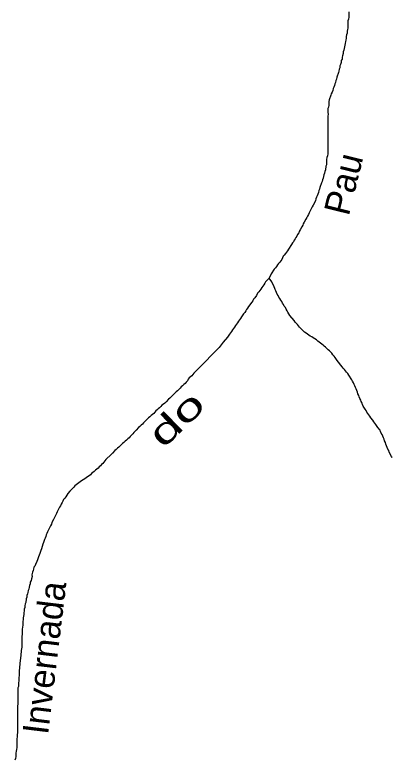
# Model space of a CAD drawing. Extents: x 652.3 to 678, y 7316.9 to 7344.9.
# Drawn here: x 662.24 to 663.41, y 7328.056 to 7330.367 of the extents above; entities that cross this region are included whole.
import ezdxf
from ezdxf.enums import TextEntityAlignment as Align

# ---------------------------------------------------------------- set-up
doc = ezdxf.new("R2010")
doc.units = 0
doc.header["$LTSCALE"] = 0.032
doc.layers.add('61', color=7, linetype='Continuous')
doc.layers.add('7', color=7, linetype='Continuous', lineweight=25)

msp = doc.modelspace()

# ---------------------------------------------------------------- linework, layer by layer
at = {"layer": '7'}
for points in [[(663.275, 7330.3769), (663.275, 7330.3602), (663.2742, 7330.3546), (663.2727, 7330.349), (663.2719, 7330.3434), (663.2719, 7330.3379), (663.2727, 7330.3323), (663.2727, 7330.3267), (663.2711, 7330.322), (663.2703, 7330.3164), (663.2703, 7330.3108), (663.2687, 7330.3053), (663.2671, 7330.3005), (663.2671, 7330.2949), (663.2663, 7330.2893), (663.2647, 7330.2846), (663.2639, 7330.279), (663.2631, 7330.2734), (663.2615, 7330.2687), (663.2607, 7330.2631)], [(663.2607, 7330.2631), (663.2599, 7330.2575), (663.2583, 7330.2527), (663.2575, 7330.2472), (663.2559, 7330.2408), (663.2544, 7330.236), (663.2544, 7330.2305), (663.252, 7330.2257), (663.2512, 7330.2201), (663.2496, 7330.2137), (663.248, 7330.209), (663.2472, 7330.2034), (663.2456, 7330.1986), (663.2448, 7330.1931), (663.2432, 7330.1883), (663.2384, 7330.174), (663.2376, 7330.1684), (663.2353, 7330.1636), (663.2345, 7330.1581), (663.2321, 7330.1533), (663.2305, 7330.1485), (663.2289, 7330.1437), (663.2273, 7330.139), (663.2257, 7330.1334), (663.2233, 7330.1278), (663.2209, 7330.123), (663.2193, 7330.1183), (663.2146, 7330.1039), (663.213, 7330.0992), (663.213, 7330.0872), (663.2122, 7330.0817), (663.2106, 7330.0769), (663.2106, 7330.065), (663.2114, 7330.0594), (663.2106, 7330.053), (663.2106, 7330.0419), (663.2098, 7330.0363), (663.2098, 7329.9361), (663.209, 7329.9305), (663.2074, 7329.9249), (663.2066, 7329.9193), (663.2066, 7329.9082), (663.2058, 7329.9026), (663.2042, 7329.8979), (663.2026, 7329.8867), (663.201, 7329.8819), (663.2002, 7329.8764), (663.1979, 7329.8716), (663.1971, 7329.866), (663.1955, 7329.8613), (663.1939, 7329.8557), (663.1923, 7329.8509), (663.1907, 7329.8461), (663.1859, 7329.8318), (663.1843, 7329.827), (663.1827, 7329.8223), (663.1811, 7329.8167), (663.1788, 7329.8111), (663.1772, 7329.8064), (663.1748, 7329.8016), (663.1732, 7329.7968), (663.1716, 7329.7912), (663.1644, 7329.7769), (663.1621, 7329.7721), (663.1549, 7329.7578), (663.1525, 7329.753), (663.1501, 7329.7483), (663.1469, 7329.7435), (663.1453, 7329.7387), (663.1422, 7329.7339), (663.1374, 7329.7244), (663.1342, 7329.7196), (663.1326, 7329.7149), (663.1294, 7329.7101), (663.1247, 7329.7005), (663.1215, 7329.6958), (663.1199, 7329.691), (663.1167, 7329.6862), (663.1143, 7329.6814), (663.1111, 7329.6775), (663.1087, 7329.6727), (663.1056, 7329.6687), (663.104, 7329.6639), (663.1008, 7329.66), (663.0976, 7329.6552), (663.0881, 7329.6409), (663.0849, 7329.6361), (663.0817, 7329.6313), (663.0785, 7329.6273), (663.0753, 7329.6226), (663.0721, 7329.6186), (663.0674, 7329.609), (663.0642, 7329.605), (663.061, 7329.6003), (663.0578, 7329.5963), (663.0546, 7329.5923), (663.0514, 7329.5875), (663.0483, 7329.5828), (663.0443, 7329.5788), (663.0347, 7329.5645), (663.0284, 7329.5509)], [(663.0284, 7329.5509), (663.0172, 7329.5398), (663.0148, 7329.535), (663.0117, 7329.5303), (663.0085, 7329.5263), (663.0053, 7329.5215), (663.0021, 7329.5167), (662.9989, 7329.5127), (662.9958, 7329.508), (662.9926, 7329.504), (662.9886, 7329.4968), (662.9838, 7329.4897), (662.9798, 7329.4857), (662.9775, 7329.4809), (662.9743, 7329.4769), (662.9647, 7329.4626), (662.9615, 7329.4578), (662.9584, 7329.4539), (662.956, 7329.4491), (662.9528, 7329.4443), (662.9488, 7329.4403), (662.9424, 7329.4308), (662.9393, 7329.426), (662.9361, 7329.4212), (662.9329, 7329.4173), (662.9297, 7329.4125), (662.9273, 7329.4077), (662.9241, 7329.4037), (662.921, 7329.399), (662.9178, 7329.395), (662.9146, 7329.3902), (662.9114, 7329.3854), (662.905, 7329.3775), (662.8987, 7329.3679), (662.8859, 7329.352), (662.8828, 7329.348), (662.8732, 7329.3361), (662.8573, 7329.3202), (662.8541, 7329.3162), (662.8263, 7329.2884), (662.8223, 7329.2844), (662.7984, 7329.2605), (662.7952, 7329.2565)], [(663.0491, 7329.5112), (663.0467, 7329.5159), (663.0427, 7329.5271), (663.0387, 7329.5342), (663.0363, 7329.539), (663.0284, 7329.5509)], [(663.4096, 7328.9948), (663.4094, 7328.9951), (663.4079, 7328.9979), (663.4008, 7329.0115), (663.3992, 7329.0162), (663.396, 7329.021), (663.3944, 7329.0258), (663.392, 7329.0306), (663.3904, 7329.0361), (663.3888, 7329.0417), (663.3864, 7329.0465), (663.3848, 7329.0512), (663.3825, 7329.056), (663.3809, 7329.0608), (663.3785, 7329.0656), (663.3761, 7329.0703), (663.3737, 7329.0751), (663.3721, 7329.0799), (663.3657, 7329.0879), (663.3594, 7329.0974), (663.353, 7329.1054), (663.3498, 7329.1101), (663.3435, 7329.1181), (663.3403, 7329.1229), (663.3339, 7329.1308), (663.3315, 7329.1356), (663.3291, 7329.1404), (663.326, 7329.1443), (663.3196, 7329.1539), (663.318, 7329.1587), (663.3164, 7329.1634), (663.314, 7329.1682), (663.3124, 7329.173), (663.31, 7329.1778), (663.3077, 7329.1825), (663.3061, 7329.1873), (663.3037, 7329.1921), (663.3021, 7329.1977), (663.3005, 7329.2024), (663.2981, 7329.2072), (663.2965, 7329.212), (663.2941, 7329.2168), (663.2917, 7329.2215), (663.2902, 7329.2263), (663.287, 7329.2311), (663.2846, 7329.2358), (663.275, 7329.2502), (663.2719, 7329.2549), (663.2687, 7329.2597), (663.2623, 7329.2677), (663.2583, 7329.2717), (663.2551, 7329.2756), (663.2392, 7329.2955), (663.2329, 7329.3051), (663.2297, 7329.3091), (663.2257, 7329.313), (663.2225, 7329.3178), (663.2193, 7329.3218), (663.2154, 7329.3258), (663.2114, 7329.3289), (663.2074, 7329.3329), (663.2034, 7329.3369), (663.1994, 7329.3401), (663.1955, 7329.3433), (663.1915, 7329.3464), (663.1875, 7329.3496), (663.1835, 7329.3528), (663.1796, 7329.356), (663.1748, 7329.3592), (663.17, 7329.3624), (663.1652, 7329.3655), (663.1605, 7329.3687), (663.1557, 7329.3711), (663.1517, 7329.3743), (663.1469, 7329.3775), (663.143, 7329.3807), (663.1382, 7329.3838), (663.1342, 7329.3878), (663.1302, 7329.391), (663.1223, 7329.399), (663.1191, 7329.4029), (663.1159, 7329.4069), (663.1119, 7329.4109), (663.1087, 7329.4149), (663.1056, 7329.4197), (663.0928, 7329.4356), (663.0865, 7329.4451), (663.0841, 7329.4499), (663.0809, 7329.4547), (663.0785, 7329.4594), (663.0753, 7329.4642), (663.0729, 7329.469), (663.0698, 7329.4738), (663.0674, 7329.4785), (663.0642, 7329.4825), (663.0618, 7329.4873), (663.0586, 7329.4921), (663.0562, 7329.4968), (663.053, 7329.5016), (663.0514, 7329.5064), (663.0491, 7329.5112)], [(662.7952, 7329.2565), (662.7913, 7329.2526), (662.7881, 7329.2478), (662.7841, 7329.2446), (662.7801, 7329.2414), (662.7769, 7329.2374), (662.7746, 7329.2327), (662.7706, 7329.2287), (662.7674, 7329.2247), (662.7634, 7329.2207), (662.7594, 7329.2168), (662.7555, 7329.2136), (662.7523, 7329.2096), (662.7483, 7329.2056), (662.7443, 7329.2016), (662.7403, 7329.1985), (662.7284, 7329.1865), (662.7244, 7329.1825), (662.7204, 7329.1786), (662.7165, 7329.1754), (662.7085, 7329.1674), (662.7045, 7329.1634), (662.7006, 7329.1603), (662.6958, 7329.1571), (662.6926, 7329.1531), (662.6886, 7329.1491), (662.6846, 7329.1459), (662.6807, 7329.1428), (662.6767, 7329.1396), (662.6735, 7329.1356), (662.6703, 7329.1316), (662.6663, 7329.1276), (662.6624, 7329.1245), (662.6584, 7329.1205), (662.6544, 7329.1173), (662.6504, 7329.1133), (662.6464, 7329.1101), (662.6425, 7329.1062), (662.6385, 7329.1022), (662.6353, 7329.0982), (662.6313, 7329.095), (662.6273, 7329.091), (662.6234, 7329.0879), (662.6154, 7329.0799), (662.609, 7329.0719), (662.6051, 7329.068), (662.5971, 7329.06), (662.5939, 7329.056), (662.59, 7329.0528), (662.586, 7329.0489), (662.582, 7329.0457), (662.578, 7329.0417), (662.574, 7329.0385), (662.5621, 7329.0266), (662.5581, 7329.0234), (662.5541, 7329.0194), (662.5502, 7329.0162), (662.5422, 7329.0083), (662.5382, 7329.0043), (662.5223, 7328.9884), (662.516, 7328.9804), (662.512, 7328.9765), (662.5088, 7328.9725), (662.5056, 7328.9685), (662.5016, 7328.9653), (662.4977, 7328.9613), (662.4937, 7328.9582), (662.4897, 7328.955), (662.4857, 7328.9518), (662.4817, 7328.9478), (662.4778, 7328.9446), (662.4738, 7328.9414), (662.4698, 7328.9383), (662.465, 7328.9351), (662.461, 7328.9319), (662.4563, 7328.9287), (662.4515, 7328.9255), (662.4467, 7328.9223), (662.442, 7328.9192), (662.438, 7328.916), (662.434, 7328.9128), (662.43, 7328.9096), (662.426, 7328.9064), (662.4221, 7328.9025), (662.4101, 7328.8905), (662.4038, 7328.8826), (662.3974, 7328.873), (662.3942, 7328.8682), (662.391, 7328.8643), (662.3886, 7328.8595), (662.3863, 7328.8547), (662.3831, 7328.8499), (662.3807, 7328.8452), (662.3783, 7328.8404), (662.3711, 7328.8261), (662.3687, 7328.8213), (662.3616, 7328.807), (662.3592, 7328.8022), (662.3544, 7328.7926), (662.3528, 7328.7879), (662.3497, 7328.7831)], [(662.3497, 7328.7831), (662.3481, 7328.7783), (662.3433, 7328.7688), (662.3409, 7328.764), (662.3393, 7328.7592), (662.3369, 7328.7545), (662.3353, 7328.7497), (662.3337, 7328.7449), (662.3314, 7328.7401), (662.3282, 7328.7306), (662.3266, 7328.7258), (662.3218, 7328.7115), (662.3202, 7328.7067), (662.317, 7328.6972), (662.3154, 7328.6916), (662.3131, 7328.6868), (662.3099, 7328.6773), (662.3083, 7328.6725), (662.3035, 7328.663), (662.3019, 7328.6582), (662.2987, 7328.6542), (662.2979, 7328.6486), (662.2963, 7328.6439), (662.294, 7328.6391), (662.2924, 7328.6311), (662.2932, 7328.6256), (662.2908, 7328.6184), (662.29, 7328.6128), (662.2876, 7328.6081), (662.2868, 7328.6025), (662.2852, 7328.5977), (662.2836, 7328.5921), (662.2828, 7328.5866), (662.2812, 7328.5818), (662.2804, 7328.5762), (662.2788, 7328.5714), (662.2772, 7328.5667), (662.2764, 7328.5611), (662.2749, 7328.5563), (662.2733, 7328.5452), (662.2717, 7328.5404), (662.2709, 7328.5348), (662.2701, 7328.5293), (662.2685, 7328.5245), (662.2685, 7328.5189), (662.2677, 7328.5134), (662.2677, 7328.5078), (662.2669, 7328.5022), (662.2653, 7328.4974), (662.2653, 7328.4919), (662.2645, 7328.4863), (662.2645, 7328.4752), (662.2629, 7328.4688), (662.2621, 7328.4624), (662.2621, 7328.4457), (662.2613, 7328.4402), (662.2613, 7328.4067), (662.2605, 7328.4012), (662.2589, 7328.3964), (662.2589, 7328.3908), (662.2581, 7328.3853), (662.2581, 7328.3797), (662.2574, 7328.3741), (662.2558, 7328.363), (662.255, 7328.3574), (662.255, 7328.3518), (662.2542, 7328.3463), (662.2542, 7328.3407), (662.2534, 7328.3351), (662.2526, 7328.3296), (662.2526, 7328.3184), (662.2518, 7328.3128), (662.2518, 7328.3017), (662.251, 7328.2961), (662.251, 7328.285), (662.2494, 7328.2802), (662.2494, 7328.2579), (662.2486, 7328.2524), (662.2486, 7328.2301), (662.2478, 7328.2245), (662.2478, 7328.141), (662.247, 7328.1354), (662.247, 7328.1283), (662.2462, 7328.1227), (662.2462, 7328.106), (662.2454, 7328.1004), (662.2454, 7328.0948), (662.2446, 7328.0893), (662.2438, 7328.0837), (662.243, 7328.0781), (662.2422, 7328.0726), (662.2422, 7328.067), (662.2414, 7328.0614), (662.2398, 7328.0558)]]:
    msp.add_lwpolyline(points, dxfattribs=at)

# ---------------------------------------------------------------- texts
at = {"layer": '61'}
for s, rotation, p in [('Pau', 76.121, (663.2978, 7329.8334)), ('Invernada', 83.128, (662.371, 7328.3691))]:
    msp.add_text(s, height=0.08, rotation=rotation, dxfattribs=at).set_placement(p, align=Align.CENTER)
at = {"layer": '61', "width": 1.6}
msp.add_text('do', height=0.08, rotation=44.039, dxfattribs=at).set_placement((662.7682, 7329.0861), align=Align.CENTER)

doc.saveas('drawing.dxf')
